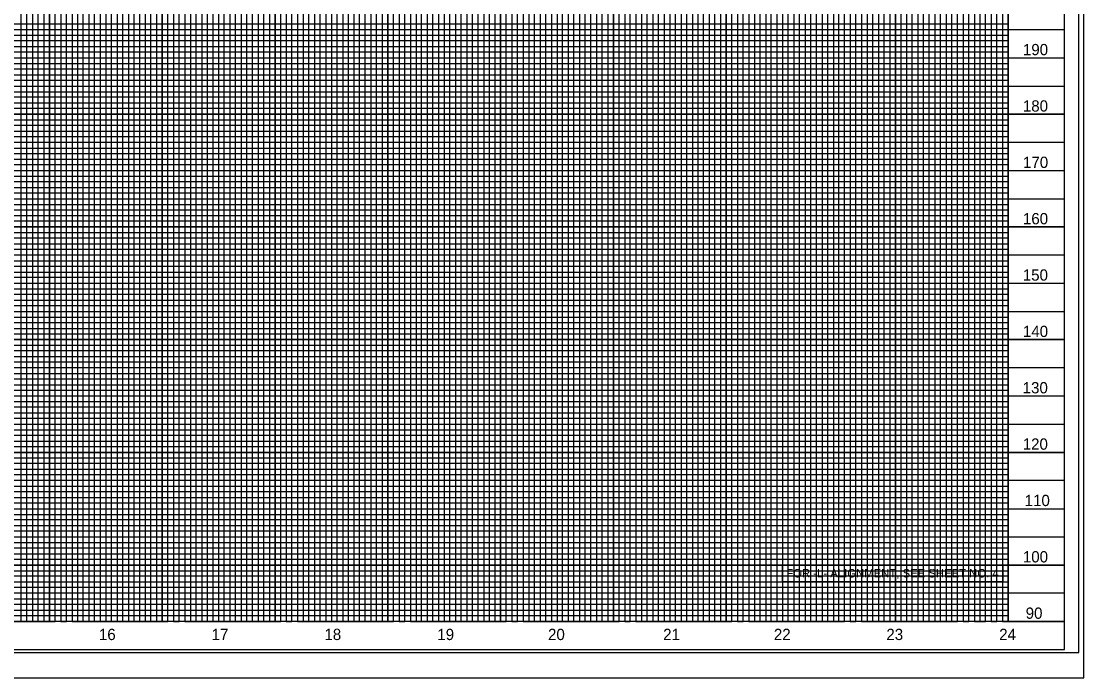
# Model space of a CAD drawing. Extents: x 1728093 to 1729777, y 538013 to 539113.
# Drawn here: x 1728835 to 1729777, y 538013 to 538595 of the extents above; entities that cross this region are included whole.
import ezdxf

# ---------------------------------------------------------------- set-up
doc = ezdxf.new("R2010")
doc.units = 0
for name, color, linetype in [('Exist Vertical Profile Horizontal Axis Label Minor', 7, 'Continuous'), ('Exist Vertical Profile Vertical Axis Label', 7, 'Continuous'), ('Prop DSN Text', 7, 'Continuous'), ('Prop Grid Mask', 7, 'Continuous'), ('Scratch_Level_0', 7, 'Continuous'), ('Sheet Cutting Line CELL', 7, 'Continuous'), ('Sheet DOT Grid CELL', 7, 'Continuous'), ('Sheet Plot Border Inside CELL', 7, 'Continuous'), ('Sheet Plot Border Outside CELL', 7, 'Continuous'), ('Sheet Profile CELL', 7, 'Continuous'), ('Sheet Profile Grid Major CELL', 7, 'Continuous'), ('Sheet Profile Grid Middle CELL', 7, 'Continuous'), ('Sheet Profile Grid Minor CELL', 7, 'Continuous')]:
    doc.layers.add(name, color=color, linetype=linetype)

msp = doc.modelspace()

# ---------------------------------------------------------------- linework, layer by layer
at = {"layer": 'Prop Grid Mask'}
msp.add_lwpolyline([(1729509.89, 538112.97), (1729705.27, 538112.97), (1729705.27, 538097.97), (1729509.89, 538097.97)], close=True, dxfattribs=at)
at = {"layer": 'Scratch_Level_0'}
msp.add_lwpolyline([(1728309.89, 539087.97), (1729709.89, 539087.97), (1729709.89, 538062.97), (1728309.89, 538062.97)], close=True, dxfattribs=at)
at = {"layer": 'Sheet Cutting Line CELL'}
msp.add_line((1728092.89, 538012.97), (1729776.89, 538012.97), dxfattribs=at)
at = {"layer": 'Sheet DOT Grid CELL'}
for p, q in [((1728859.89, 539087.97), (1728859.89, 538062.97)), ((1728909.89, 539087.97), (1728909.89, 538062.97)), ((1728959.89, 539087.97), (1728959.89, 538062.97)), ((1729009.89, 539087.97), (1729009.89, 538062.97)), ((1729059.89, 539087.97), (1729059.89, 538062.97)), ((1729109.89, 539087.97), (1729109.89, 538062.97)), ((1729159.89, 539087.97), (1729159.89, 538062.97)), ((1729209.89, 539087.97), (1729209.89, 538062.97)), ((1729259.89, 539087.97), (1729259.89, 538062.97)), ((1729309.89, 539087.97), (1729309.89, 538062.97)), ((1729359.89, 539087.97), (1729359.89, 538062.97)), ((1729409.89, 539087.97), (1729409.89, 538062.97)), ((1729459.89, 539087.97), (1729459.89, 538062.97)), ((1729509.89, 539087.97), (1729509.89, 538062.97)), ((1729559.89, 538062.97), (1729559.89, 538950.42)), ((1729709.89, 538062.97), (1729709.89, 538926.92)), ((1729609.89, 538062.97), (1729609.89, 538867.97)), ((1729659.89, 538062.97), (1729659.89, 538867.98)), ((1728259.89, 538562.97), (1729759.89, 538562.97)), ((1728259.89, 538512.97), (1729759.89, 538512.97)), ((1728259.89, 538462.97), (1729759.89, 538462.97)), ((1728259.89, 538412.97), (1729759.89, 538412.97)), ((1728259.89, 538362.97), (1729759.89, 538362.97)), ((1728259.89, 538312.97), (1729759.89, 538312.97)), ((1728259.89, 538262.97), (1729759.89, 538262.97)), ((1728259.89, 538212.97), (1729759.89, 538212.97)), ((1728259.89, 538162.97), (1729759.89, 538162.97)), ((1728259.89, 538112.97), (1729759.89, 538112.97))]:
    msp.add_line(p, q, dxfattribs=at)
at = {"layer": 'Sheet Plot Border Inside CELL'}
msp.add_lwpolyline([(1729772.39, 539090.52), (1728105.89, 539090.52), (1728105.89, 538035.42), (1729772.39, 538035.42)], close=True, dxfattribs=at)
at = {"layer": 'Sheet Plot Border Outside CELL'}
msp.add_lwpolyline([(1729776.89, 539112.97), (1728092.89, 539112.97), (1728092.89, 538012.97), (1729776.89, 538012.97)], close=True, dxfattribs=at)
at = {"layer": 'Sheet Profile CELL'}
msp.add_line((1729759.89, 538062.97), (1728259.89, 538062.97), dxfattribs=at)
msp.add_lwpolyline([(1729759.89, 539087.97), (1728259.89, 539087.97), (1728259.89, 538037.97), (1729759.89, 538037.97)], close=True, dxfattribs=at)
at = {"layer": 'Sheet Profile Grid Major CELL'}
for points in [[(1728809.89, 538062.97), (1728859.89, 538062.97), (1728859.89, 539087.97)], [(1728909.89, 539087.97), (1728909.89, 538062.97), (1728959.89, 538062.97), (1728959.89, 539087.97)], [(1729009.89, 539087.97), (1729009.89, 538062.97), (1729059.89, 538062.97), (1729059.89, 539087.97)], [(1729109.89, 539087.97), (1729109.89, 538062.97), (1729159.89, 538062.97), (1729159.89, 539087.97)], [(1729209.89, 539087.97), (1729209.89, 538062.97), (1729259.89, 538062.97), (1729259.89, 539087.97)], [(1729309.89, 539087.97), (1729309.89, 538062.97), (1729359.89, 538062.97), (1729359.89, 539087.97)], [(1729409.89, 539087.97), (1729409.89, 538062.97), (1729459.89, 538062.97), (1729459.89, 539087.97)], [(1729509.89, 539087.97), (1729509.89, 538062.97), (1729559.89, 538062.97), (1729559.89, 539087.97)], [(1729709.89, 538926.92), (1729709.89, 538062.97), (1729759.89, 538062.97)], [(1729609.89, 538867.97), (1729609.89, 538062.97), (1729659.89, 538062.97), (1729659.89, 538867.98)], [(1729759.89, 538512.97), (1728259.89, 538512.97), (1728259.89, 538562.97), (1729759.89, 538562.97)], [(1729759.89, 538412.97), (1728259.89, 538412.97), (1728259.89, 538462.97), (1729759.89, 538462.97)], [(1729759.89, 538312.97), (1728259.89, 538312.97), (1728259.89, 538362.97), (1729759.89, 538362.97)], [(1729759.89, 538212.97), (1728259.89, 538212.97), (1728259.89, 538262.97), (1729759.89, 538262.97)], [(1729759.89, 538112.97), (1728259.89, 538112.97), (1728259.89, 538162.97), (1729759.89, 538162.97)]]:
    msp.add_lwpolyline(points, dxfattribs=at)
at = {"layer": 'Sheet Profile Grid Middle CELL'}
for points in [[(1728784.89, 538062.97), (1728834.89, 538062.97), (1728834.89, 539087.97)], [(1728884.89, 539087.97), (1728884.89, 538062.97), (1728934.89, 538062.97), (1728934.89, 539087.97)], [(1728984.89, 539087.97), (1728984.89, 538062.97), (1729034.89, 538062.97), (1729034.89, 539087.97)], [(1729084.89, 539087.97), (1729084.89, 538062.97), (1729134.89, 538062.97), (1729134.89, 539087.97)], [(1729184.89, 539087.97), (1729184.89, 538062.97), (1729234.89, 538062.97), (1729234.89, 539087.97)], [(1729284.89, 539087.97), (1729284.89, 538062.97), (1729334.89, 538062.97), (1729334.89, 539087.97)], [(1729384.89, 539087.97), (1729384.89, 538062.97), (1729434.89, 538062.97), (1729434.89, 539087.97)], [(1729484.89, 539087.97), (1729484.89, 538062.97), (1729534.89, 538062.97), (1729534.89, 539087.97)], [(1729584.89, 538926.92), (1729584.89, 538062.97), (1729634.89, 538062.97), (1729634.89, 538867.98)], [(1729684.89, 538867.98), (1729684.89, 538062.97)], [(1729759.89, 538587.97), (1728259.89, 538587.97), (1728259.89, 538537.97), (1729759.89, 538537.97)], [(1729759.89, 538487.97), (1728259.89, 538487.97), (1728259.89, 538437.97), (1729759.89, 538437.97)], [(1729759.89, 538387.97), (1728259.89, 538387.97), (1728259.89, 538337.97), (1729759.89, 538337.97)], [(1729759.89, 538287.97), (1728259.89, 538287.97), (1728259.89, 538237.97), (1729759.89, 538237.97)], [(1729759.89, 538187.97), (1728259.89, 538187.97), (1728259.89, 538137.97), (1729759.89, 538137.97)], [(1729759.89, 538087.97), (1728259.89, 538087.97)]]:
    msp.add_lwpolyline(points, dxfattribs=at)
at = {"layer": 'Sheet Profile Grid Minor CELL'}
for points in [[(1728839.89, 538062.97), (1728839.89, 539087.97)], [(1728844.89, 539087.97), (1728844.89, 538062.97), (1728849.89, 538062.97), (1728849.89, 539087.97)], [(1728854.89, 539087.97), (1728854.89, 538062.97), (1728864.89, 538062.97), (1728864.89, 539087.97)], [(1728869.89, 539087.97), (1728869.89, 538062.97), (1728869.89, 538062.97), (1728874.89, 538062.97), (1728874.89, 539087.97)], [(1728879.89, 539087.97), (1728879.89, 538062.97), (1728889.89, 538062.97), (1728889.89, 539087.97)], [(1728894.89, 539087.97), (1728894.89, 538062.97), (1728899.89, 538062.97), (1728899.89, 539087.97)], [(1728904.89, 539087.97), (1728904.89, 538062.97), (1728914.89, 538062.97), (1728914.89, 539087.97)], [(1728919.89, 539087.97), (1728919.89, 538062.97), (1728924.89, 538062.97), (1728924.89, 539087.97)], [(1728929.89, 539087.97), (1728929.89, 538062.97), (1728939.89, 538062.97), (1728939.89, 539087.97)], [(1728944.89, 539087.97), (1728944.89, 538062.97), (1728949.89, 538062.97), (1728949.89, 539087.97)], [(1728954.89, 539087.97), (1728954.89, 538062.97), (1728964.89, 538062.97), (1728964.89, 539087.97)], [(1728969.89, 539087.97), (1728969.89, 538062.97), (1728974.89, 538062.97), (1728974.89, 539087.97)], [(1728979.89, 539087.97), (1728979.89, 538062.97), (1728989.89, 538062.97), (1728989.89, 539087.97)], [(1728994.89, 539087.97), (1728994.89, 538062.97), (1728999.89, 538062.97), (1728999.89, 539087.97)], [(1729004.89, 539087.97), (1729004.89, 538062.97), (1729014.89, 538062.97), (1729014.89, 539087.97)], [(1729019.89, 539087.97), (1729019.89, 538062.97)], [(1729029.89, 539087.37), (1729029.89, 538062.97), (1729039.89, 538062.97), (1729039.89, 539087.97)], [(1729044.89, 539087.97), (1729044.89, 538062.97), (1729049.89, 538062.97), (1729049.89, 539087.97)], [(1729054.89, 539087.97), (1729054.89, 538062.97), (1729064.89, 538062.97), (1729064.89, 539087.97)], [(1729069.89, 539087.97), (1729069.89, 538062.97), (1729074.89, 538062.97), (1729074.89, 539087.97)], [(1729079.89, 539087.97), (1729079.89, 538062.97), (1729089.89, 538062.97), (1729089.89, 539087.97)], [(1729094.89, 539087.97), (1729094.89, 538062.97), (1729099.89, 538062.97), (1729099.89, 539087.97)], [(1729104.89, 539087.97), (1729104.89, 538062.97), (1729114.89, 538062.97), (1729114.89, 539087.97)], [(1729119.89, 539087.97), (1729119.89, 538062.97), (1729124.89, 538062.97), (1729124.89, 539087.97)], [(1729129.89, 539087.97), (1729129.89, 538062.97), (1729139.89, 538062.97), (1729139.89, 539087.97)], [(1729144.89, 539087.97), (1729144.89, 538062.97), (1729149.89, 538062.97), (1729149.89, 539087.97)], [(1729154.89, 539087.97), (1729154.89, 538062.97), (1729164.89, 538062.97), (1729164.89, 539087.97)], [(1729169.89, 539087.97), (1729169.89, 538062.97), (1729174.89, 538062.97), (1729174.89, 539087.97)], [(1729179.89, 539087.97), (1729179.89, 538062.97), (1729189.89, 538062.97), (1729189.89, 539087.97)], [(1729194.89, 539087.97), (1729194.89, 538062.97), (1729199.89, 538062.97), (1729199.89, 539087.97)], [(1729204.89, 539087.97), (1729204.89, 538062.97), (1729214.89, 538062.97), (1729214.89, 539087.97)], [(1729219.89, 539087.97), (1729219.89, 538062.97), (1729224.89, 538062.97), (1729224.89, 539087.97)], [(1729229.89, 539087.97), (1729229.89, 538062.97), (1729239.89, 538062.97), (1729239.89, 539087.97)], [(1729244.89, 539087.97), (1729244.89, 538062.97), (1729249.89, 538062.97), (1729249.89, 539087.97)], [(1729254.89, 539087.97), (1729254.89, 538062.97), (1729264.89, 538062.97), (1729264.89, 539087.97)], [(1729269.89, 539087.97), (1729269.89, 538062.97), (1729274.89, 538062.97), (1729274.89, 539087.97)], [(1729279.89, 539087.97), (1729279.89, 538062.97), (1729289.89, 538062.97), (1729289.89, 539087.97)], [(1729294.89, 539087.97), (1729294.89, 538062.97), (1729299.89, 538062.97), (1729299.89, 539087.97)], [(1729304.89, 539087.97), (1729304.89, 538062.97), (1729314.89, 538062.97), (1729314.89, 539087.97)], [(1729319.89, 539087.97), (1729319.89, 538062.97), (1729324.89, 538062.97), (1729324.89, 539087.97)], [(1729329.89, 539087.97), (1729329.89, 538062.97)], [(1729329.89, 538062.97), (1729339.89, 538062.97), (1729339.89, 539087.97)], [(1729344.89, 539087.97), (1729344.89, 538062.97), (1729349.89, 538062.97), (1729349.89, 539087.97)], [(1729354.89, 539087.97), (1729354.89, 538062.97), (1729364.89, 538062.97), (1729364.89, 539087.97)], [(1729369.89, 539087.97), (1729369.89, 538062.97), (1729374.89, 538062.97), (1729374.89, 539087.97)], [(1729379.89, 539087.97), (1729379.89, 538062.97), (1729389.89, 538062.97), (1729389.89, 539087.97)], [(1729394.89, 539087.97), (1729394.89, 538062.97), (1729399.89, 538062.97), (1729399.89, 539087.97)], [(1729404.89, 539087.97), (1729404.89, 538062.97), (1729414.89, 538062.97), (1729414.89, 539087.97)], [(1729419.89, 539087.97), (1729419.89, 538062.97), (1729424.89, 538062.97), (1729424.89, 539087.97)], [(1729429.89, 539087.97), (1729429.89, 538062.97), (1729439.89, 538062.97), (1729439.89, 539087.97)], [(1729444.89, 539087.97), (1729444.89, 538062.97), (1729449.89, 538062.97), (1729449.89, 539087.97)], [(1729454.89, 539087.97), (1729454.89, 538062.97), (1729464.89, 538062.97), (1729464.89, 539087.97)], [(1729469.89, 539087.97), (1729469.89, 538062.97), (1729474.89, 538062.97), (1729474.89, 539087.97)], [(1729479.89, 539087.97), (1729479.89, 538062.97), (1729489.89, 538062.97), (1729489.89, 539087.97)], [(1729494.89, 539087.97), (1729494.89, 538062.97), (1729499.89, 538062.97), (1729499.89, 539087.97)], [(1729504.89, 539087.97), (1729504.89, 538062.97), (1729514.89, 538062.97), (1729514.89, 539087.97)], [(1729519.89, 539087.97), (1729519.89, 538062.97), (1729524.89, 538062.97), (1729524.89, 539087.97)], [(1729529.89, 539087.97), (1729529.89, 538062.97), (1729539.89, 538062.97), (1729539.89, 539087.97)], [(1729544.89, 539087.97), (1729544.89, 538062.97), (1729549.89, 538062.97), (1729549.89, 539087.97)], [(1729554.89, 539087.97), (1729554.89, 538062.97), (1729564.89, 538062.97), (1729564.89, 538926.92)], [(1729019.89, 538062.97), (1729024.89, 538062.97), (1729024.89, 539087.37)], [(1729569.89, 538926.92), (1729569.89, 538062.97), (1729574.89, 538062.97), (1729574.89, 538926.92)], [(1729579.89, 538926.92), (1729579.89, 538062.97), (1729589.89, 538062.97), (1729589.89, 538926.92)], [(1729594.89, 538926.92), (1729594.89, 538062.97), (1729599.89, 538062.97), (1729599.89, 538926.92)], [(1729604.89, 538867.97), (1729604.89, 538062.97), (1729614.89, 538062.97), (1729614.89, 538867.97)], [(1729619.89, 538867.97), (1729619.89, 538062.97), (1729624.89, 538062.97), (1729624.89, 538867.98)], [(1729629.89, 538867.98), (1729629.89, 538062.97), (1729639.89, 538062.97), (1729639.89, 538867.98)], [(1729644.89, 538062.97), (1729649.89, 538062.97), (1729649.89, 538867.98)], [(1729644.89, 538867.98), (1729644.89, 538062.97)], [(1729654.89, 538867.98), (1729654.89, 538062.97), (1729664.89, 538062.97), (1729664.89, 538867.98)], [(1729669.89, 538867.98), (1729669.89, 538062.97), (1729674.89, 538062.97), (1729674.89, 538867.98)], [(1729679.89, 538867.98), (1729679.89, 538062.97), (1729689.89, 538062.97), (1729689.89, 538867.98)], [(1729694.89, 538867.98), (1729694.89, 538062.97), (1729699.89, 538062.97), (1729699.89, 538867.98)], [(1729704.89, 538867.99), (1729704.89, 538062.97), (1729714.89, 538062.97)], [(1729709.89, 538592.97), (1728309.89, 538592.97), (1728309.89, 538582.97), (1729709.89, 538582.97)], [(1729709.89, 538577.97), (1728309.89, 538577.97), (1728309.89, 538572.97), (1729709.89, 538572.97)], [(1729709.89, 538567.97), (1728309.89, 538567.97)], [(1728309.89, 538557.97), (1729709.89, 538557.97)], [(1729709.89, 538552.97), (1728309.89, 538552.97), (1728309.89, 538547.97), (1729709.89, 538547.97)], [(1729709.89, 538542.97), (1728309.89, 538542.97), (1728309.89, 538532.97), (1729709.89, 538532.97)], [(1729709.89, 538527.97), (1728309.89, 538527.97), (1728309.89, 538522.97), (1729709.89, 538522.97)], [(1729709.89, 538517.97), (1728309.89, 538517.97), (1728309.89, 538507.97), (1729709.89, 538507.97)], [(1729709.89, 538502.97), (1728309.89, 538502.97), (1728309.89, 538497.97), (1729709.89, 538497.97)], [(1729709.89, 538492.97), (1728309.89, 538492.97), (1728309.89, 538482.97), (1729709.89, 538482.97)], [(1729709.89, 538477.97), (1728309.89, 538477.97), (1728309.89, 538472.97), (1729709.89, 538472.97)], [(1729709.89, 538467.97), (1728309.89, 538467.97), (1728309.89, 538457.97), (1729709.89, 538457.97)], [(1729709.89, 538452.97), (1728309.89, 538452.97), (1728309.89, 538447.97), (1729709.89, 538447.97)], [(1729709.89, 538442.97), (1728309.89, 538442.97), (1728309.89, 538432.97), (1729709.89, 538432.97)], [(1729709.89, 538427.97), (1728309.89, 538427.97), (1728309.89, 538422.97), (1729709.89, 538422.97)], [(1729709.89, 538417.97), (1728309.89, 538417.97), (1728309.89, 538407.97), (1729709.89, 538407.97)], [(1729709.89, 538402.97), (1728309.89, 538402.97), (1728309.89, 538397.97), (1729709.89, 538397.97)], [(1729709.89, 538392.97), (1728309.89, 538392.97), (1728309.89, 538382.97), (1729709.89, 538382.97)], [(1729709.89, 538377.97), (1728309.89, 538377.97), (1728309.89, 538372.97), (1729709.89, 538372.97)], [(1729709.89, 538367.97), (1728309.89, 538367.97), (1728309.89, 538357.97), (1729709.89, 538357.97)], [(1729709.89, 538352.97), (1728309.89, 538352.97), (1728309.89, 538347.97), (1729709.89, 538347.97)], [(1729709.89, 538342.97), (1728309.89, 538342.97), (1728309.89, 538332.97), (1729709.89, 538332.97)], [(1729709.89, 538327.97), (1728309.89, 538327.97), (1728309.89, 538322.97), (1729709.89, 538322.97)], [(1729709.89, 538317.97), (1728309.89, 538317.97), (1728309.89, 538307.97), (1729709.89, 538307.97)], [(1729709.89, 538302.97), (1728309.89, 538302.97), (1728309.89, 538297.97), (1729709.89, 538297.97)], [(1729709.89, 538292.97), (1728309.89, 538292.97), (1728309.89, 538282.97), (1729709.89, 538282.97)], [(1729709.89, 538277.97), (1728309.89, 538277.97), (1728309.89, 538272.97), (1729709.89, 538272.97)], [(1729709.89, 538267.97), (1728309.89, 538267.97)], [(1728309.89, 538257.97), (1729709.89, 538257.97)], [(1729709.89, 538252.97), (1728309.89, 538252.97), (1728309.89, 538247.97), (1729709.89, 538247.97)], [(1729709.89, 538242.97), (1728309.89, 538242.97)], [(1728309.89, 538232.97), (1729709.89, 538232.97)], [(1729709.89, 538227.97), (1728309.89, 538227.97), (1728309.89, 538222.97), (1729709.89, 538222.97)], [(1729709.89, 538217.97), (1728309.89, 538217.97), (1728309.89, 538207.97), (1729709.89, 538207.97)], [(1729709.89, 538202.97), (1728309.89, 538202.97), (1728309.89, 538197.97), (1729709.89, 538197.97)], [(1729709.89, 538192.97), (1728309.89, 538192.97), (1728309.89, 538182.97), (1729709.89, 538182.97)], [(1729709.89, 538177.97), (1728309.89, 538177.97), (1728309.89, 538172.97), (1729709.89, 538172.97)], [(1729709.89, 538167.97), (1728309.89, 538167.97), (1728309.89, 538157.97), (1729709.89, 538157.97)], [(1729709.89, 538152.97), (1728309.89, 538152.97), (1728309.89, 538147.97), (1729709.89, 538147.97)], [(1729709.89, 538142.97), (1728309.89, 538142.97), (1728309.89, 538132.97), (1729709.89, 538132.97)], [(1729709.89, 538127.97), (1728309.89, 538127.97), (1728309.89, 538122.97), (1729709.89, 538122.97)], [(1729709.89, 538117.97), (1728309.89, 538117.97), (1728309.89, 538107.97), (1729709.89, 538107.97)], [(1729709.89, 538102.97), (1728309.89, 538102.97), (1728309.89, 538097.97), (1729709.89, 538097.97)], [(1729709.89, 538092.97), (1728309.89, 538092.97), (1728309.89, 538082.97), (1729709.89, 538082.97)], [(1729709.89, 538077.97), (1728309.89, 538077.97), (1728309.89, 538072.97), (1729709.89, 538072.97)], [(1729709.89, 538067.97), (1728309.89, 538067.97)]]:
    msp.add_lwpolyline(points, dxfattribs=at)

# ---------------------------------------------------------------- texts
at = {"layer": 'Exist Vertical Profile Horizontal Axis Label Minor'}
for s, p in [('16', (1728903.74, 538046.42)), ('17', (1729003.68, 538046.42)), ('18', (1729103.68, 538046.42)), ('19', (1729203.77, 538046.42)), ('20', (1729301.93, 538046.42)), ('21', (1729404, 538046.42)), ('22', (1729502.15, 538046.42)), ('23', (1729601.92, 538046.42)), ('24', (1729701.92, 538046.42))]:
    msp.add_text(s, height=10, dxfattribs=at).set_placement(p)
at = {"layer": 'Exist Vertical Profile Vertical Axis Label'}
for s, p in [('190', (1729722.97, 538565.31)), ('180', (1729722.91, 538515.31)), ('170', (1729723.06, 538465.31)), ('160', (1729722.97, 538415.31)), ('150', (1729722.84, 538365.31)), ('140', (1729722.97, 538315.31)), ('130', (1729722.75, 538265.31)), ('120', (1729722.78, 538215.31)), ('110', (1729724.51, 538165.31)), ('100', (1729722.91, 538115.31)), ('90', (1729725.41, 538065.31))]:
    msp.add_text(s, height=10, dxfattribs=at).set_placement(p)
at = {"layer": 'Prop DSN Text'}
msp.add_text('FOR -L- ALIGNMENT, SEE SHEET NO. 4', height=7.5, dxfattribs=at).set_placement((1729513.15, 538101.95))

doc.saveas('drawing.dxf')
